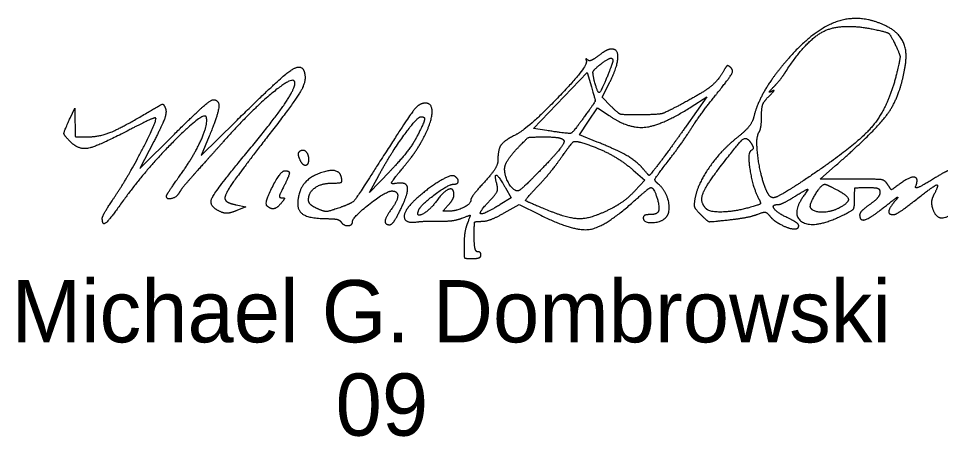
# Model space of a CAD drawing. Extents: x 0 to 40.2, y 0 to 22.
# Drawn here: x 37.037 to 39.11, y 9.704 to 10.644 of the extents above; entities that cross this region are included whole.
import ezdxf

# ---------------------------------------------------------------- set-up
doc = ezdxf.new("R2010")
doc.units = 0
doc.layers.add('SH_Text', color=7, linetype='Continuous')

msp = doc.modelspace()

# ---------------------------------------------------------------- linework, layer by layer
at = {"layer": 'SH_Text'}
for p, q in [((37.6689, 10.3288), (37.6689, 10.3288)), ((37.5957, 10.223), (37.5957, 10.223)), ((37.2255, 10.1947), (37.2255, 10.1947))]:
    msp.add_line(p, q, dxfattribs=at)
for points in [[(38.2249, 10.3922), (38.1945, 10.3971), (38.3154, 10.5228), (38.3249, 10.4906)], [(38.3688, 10.4472), (38.3489, 10.467), (38.3648, 10.4981)], [(38.5493, 10.4456), (38.5844, 10.4678), (38.5376, 10.4018)], [(37.153, 10.4197), (37.1634, 10.4425), (37.1641, 10.4102)], [(38.3382, 10.3664), (38.298, 10.3828), (38.3184, 10.4132), (38.3389, 10.4436), (38.3647, 10.4259)], [(37.4659, 10.3796), (37.4479, 10.3361), (37.5249, 10.4121)], [(37.3414, 10.3677), (37.3101, 10.307), (37.3876, 10.3842)], [(38.4187, 10.3034), (38.4453, 10.2805), (38.4225, 10.2563)], [(38.9111, 10.2829), (38.8389, 10.2829), (38.8737, 10.3133)], [(37.8715, 10.3001), (37.8261, 10.2525), (37.8469, 10.2911)], [(38.1316, 10.2636), (38.1447, 10.2406), (38.1202, 10.2257)], [(37.5263, 10.2252), (37.5485, 10.2207), (37.5276, 10.2121)], [(38.129, 10.2071), (38.1622, 10.2261), (38.2081, 10.2032)]]:
    msp.add_lwpolyline(points, dxfattribs=at)
for points in [[(38.9887, 10.6266), (38.9318, 10.655), (38.8265, 10.6208), (38.7688, 10.5553)], [(38.7607, 10.5229), (38.8078, 10.5965), (38.8883, 10.6353), (38.9617, 10.6196)], [(38.9617, 10.6196), (38.9893, 10.6138), (38.9972, 10.6079), (39.0077, 10.5859)], [(39.0304, 10.5375), (39.0358, 10.5703), (39.0158, 10.613), (38.9887, 10.6266)], [(38.3703, 10.5755), (38.3646, 10.5755), (38.3514, 10.5688), (38.3409, 10.5605)], [(38.3648, 10.4981), (38.3831, 10.534), (38.386, 10.5755), (38.3703, 10.5755)], [(39.0077, 10.5859), (39.0185, 10.5631), (39.019, 10.5536), (39.0113, 10.5217)], [(38.3165, 10.551), (38.3135, 10.554), (38.3122, 10.5528), (38.3135, 10.5483)], [(38.3409, 10.5605), (38.3305, 10.5523), (38.3195, 10.548), (38.3165, 10.551)], [(38.3429, 10.5392), (38.3589, 10.5521), (38.3731, 10.5568), (38.3731, 10.549)], [(38.7688, 10.5553), (38.7352, 10.5171), (38.6973, 10.4533), (38.6897, 10.4222)], [(37.5249, 10.4121), (37.6193, 10.5054), (37.6718, 10.5443), (37.6787, 10.5262)], [(38.3135, 10.5483), (38.3172, 10.5365), (38.1841, 10.3976), (38.1548, 10.3827)], [(38.3315, 10.505), (38.3275, 10.5211), (38.33, 10.5288), (38.3429, 10.5392)], [(38.3731, 10.549), (38.3731, 10.547), (38.3676, 10.5317), (38.3609, 10.5148)], [(38.6078, 10.4763), (38.6357, 10.5111), (38.6446, 10.5274), (38.6387, 10.5332)], [(38.6387, 10.5332), (38.6329, 10.5389), (38.6283, 10.5374), (38.623, 10.5279)], [(38.8737, 10.3133), (38.9659, 10.394), (39.0193, 10.4704), (39.0304, 10.5375)], [(37.6787, 10.5262), (37.6856, 10.5082), (37.6636, 10.4649), (37.6168, 10.4045)], [(38.3609, 10.5148), (38.3465, 10.479), (38.3387, 10.4764), (38.3315, 10.505)], [(38.623, 10.5279), (38.6099, 10.5047), (38.5766, 10.4779), (38.5292, 10.4525)], [(38.7341, 10.4898), (38.7424, 10.4982), (38.7544, 10.5131), (38.7607, 10.5229)], [(39.0113, 10.5217), (38.9925, 10.4431), (38.916, 10.3551), (38.7996, 10.2782)], [(37.6567, 10.504), (37.6489, 10.5118), (37.558, 10.4347), (37.5055, 10.376)], [(37.5636, 10.3589), (37.6178, 10.4243), (37.6641, 10.4966), (37.6567, 10.504)], [(38.3249, 10.4906), (38.334, 10.4597), (38.3335, 10.4573), (38.3096, 10.4239)], [(38.7303, 10.4805), (38.724, 10.4772), (38.7257, 10.4813), (38.7341, 10.4898)], [(38.5495, 10.397), (38.56, 10.4138), (38.5862, 10.4494), (38.6078, 10.4763)], [(38.7074, 10.4251), (38.7074, 10.4442), (38.713, 10.4586), (38.7246, 10.4699)], [(38.7246, 10.4699), (38.734, 10.4791), (38.7366, 10.4838), (38.7303, 10.4805)], [(37.3256, 10.4319), (37.3586, 10.4513), (37.3634, 10.4524), (37.3677, 10.4411)], [(37.3876, 10.3842), (37.4303, 10.4267), (37.4694, 10.4615), (37.4745, 10.4615)], [(37.4745, 10.4615), (37.4892, 10.4615), (37.4856, 10.4273), (37.4659, 10.3796)], [(37.9517, 10.4539), (37.9377, 10.4539), (37.9118, 10.4203), (37.8441, 10.3142)], [(37.9467, 10.374), (37.9655, 10.4096), (37.9682, 10.4539), (37.9517, 10.4539)], [(38.436, 10.4276), (38.3949, 10.4273), (38.386, 10.4299), (38.3688, 10.4472)], [(38.5292, 10.4525), (38.4918, 10.4324), (38.4745, 10.4278), (38.436, 10.4276)], [(37.1903, 10.3779), (37.2182, 10.3779), (37.2673, 10.3975), (37.3256, 10.4319)], [(37.3677, 10.4411), (37.3706, 10.4333), (37.3603, 10.4044), (37.3414, 10.3677)], [(38.3647, 10.4259), (38.4089, 10.3957), (38.4832, 10.4036), (38.5493, 10.4456)], [(37.1546, 10.3663), (37.1394, 10.3814), (37.1392, 10.3896), (37.153, 10.4197)], [(37.1641, 10.4102), (37.1647, 10.3787), (37.1653, 10.3779), (37.1903, 10.3779)], [(37.2529, 10.2422), (37.2827, 10.2864), (37.3498, 10.4157), (37.3452, 10.4203)], [(37.4597, 10.4215), (37.4564, 10.4382), (37.3228, 10.3048), (37.2733, 10.2354)], [(37.3452, 10.4203), (37.3437, 10.4218), (37.3168, 10.4096), (37.2855, 10.3932)], [(37.3964, 10.2856), (37.4293, 10.3313), (37.463, 10.4039), (37.4597, 10.4215)], [(37.8469, 10.2911), (37.8713, 10.3365), (37.9336, 10.4233), (37.9418, 10.4234)], [(37.9418, 10.4234), (37.9513, 10.4235), (37.9483, 10.4092), (37.9322, 10.3777)], [(38.3096, 10.4239), (38.2836, 10.3877), (38.2746, 10.3843), (38.2249, 10.3922)], [(38.6897, 10.4222), (38.6869, 10.4111), (38.6709, 10.391), (38.654, 10.3776)], [(38.701, 10.3871), (38.7045, 10.3925), (38.7073, 10.4096), (38.7074, 10.4251)], [(37.2855, 10.3932), (37.2162, 10.3569), (37.1729, 10.348), (37.1546, 10.3663)], [(37.6168, 10.4045), (37.5391, 10.3041), (37.4988, 10.2458), (37.5014, 10.2378)], [(38.5376, 10.4018), (38.5119, 10.3654), (38.4836, 10.3264), (38.4746, 10.315)], [(38.4975, 10.3236), (38.5156, 10.3472), (38.539, 10.3802), (38.5495, 10.397)], [(38.7164, 10.262), (38.7041, 10.2935), (38.694, 10.376), (38.701, 10.3871)], [(37.5055, 10.376), (37.4748, 10.3417), (37.4394, 10.3021), (37.4269, 10.2881)], [(37.9322, 10.3777), (37.9237, 10.3612), (37.8964, 10.3262), (37.8715, 10.3001)], [(37.9002, 10.307), (37.917, 10.3272), (37.9379, 10.3573), (37.9467, 10.374)], [(38.1548, 10.3827), (38.1281, 10.369), (38.1147, 10.3497), (38.1147, 10.325)], [(38.1561, 10.3494), (38.1797, 10.375), (38.1861, 10.3779), (38.2202, 10.3779)], [(38.263, 10.3701), (38.2656, 10.3659), (38.2447, 10.3385), (38.2166, 10.3093)], [(38.2202, 10.3779), (38.2411, 10.3779), (38.2603, 10.3744), (38.263, 10.3701)], [(38.2593, 10.3343), (38.2795, 10.3631), (38.2878, 10.3695), (38.3003, 10.3658)], [(38.3003, 10.3658), (38.3361, 10.3554), (38.3938, 10.3249), (38.4187, 10.3034)], [(38.4416, 10.3056), (38.4279, 10.3221), (38.3844, 10.3477), (38.3382, 10.3664)], [(38.654, 10.3776), (38.6178, 10.349), (38.5647, 10.2737), (38.5583, 10.2421)], [(38.6144, 10.3104), (38.6571, 10.3663), (38.6743, 10.3792), (38.6845, 10.3629)], [(37.4959, 10.2077), (37.4632, 10.2202), (37.4803, 10.2583), (37.5636, 10.3589)], [(37.6689, 10.3288), (37.6664, 10.3353), (37.6663, 10.3425), (37.6686, 10.3448)], [(37.6686, 10.3448), (37.6753, 10.3514), (37.6891, 10.3401), (37.6891, 10.328)], [(38.1299, 10.3055), (38.1299, 10.314), (38.1417, 10.3337), (38.1561, 10.3494)], [(38.6835, 10.3468), (38.6752, 10.3416), (38.6875, 10.2647), (38.7008, 10.2396)], [(38.6845, 10.3629), (38.6889, 10.3558), (38.6886, 10.3499), (38.6835, 10.3468)], [(37.6891, 10.328), (37.6891, 10.3135), (37.6746, 10.314), (37.6689, 10.3288)], [(38.1147, 10.325), (38.1147, 10.3163), (38.101, 10.2943), (38.0843, 10.2762)], [(38.207, 10.2696), (38.2218, 10.2853), (38.2453, 10.3144), (38.2593, 10.3343)], [(38.4757, 10.2715), (38.4662, 10.2793), (38.4694, 10.287), (38.4975, 10.3236)], [(37.5957, 10.223), (37.5894, 10.2293), (37.6265, 10.3019), (37.636, 10.3019)], [(37.636, 10.3019), (37.6466, 10.3019), (37.6453, 10.2894), (37.6319, 10.2635)], [(37.7632, 10.2861), (37.7581, 10.311), (37.679, 10.2845), (37.6696, 10.2546)], [(37.8441, 10.3142), (37.7965, 10.2396), (37.7865, 10.2284), (37.7592, 10.2187)], [(37.8829, 10.2728), (37.8737, 10.2712), (37.879, 10.2816), (37.9002, 10.307)], [(38.1595, 10.2563), (38.1496, 10.2563), (38.1299, 10.2891), (38.1299, 10.3055)], [(38.2166, 10.3093), (38.1884, 10.2802), (38.1627, 10.2563), (38.1595, 10.2563)], [(38.4746, 10.315), (38.4557, 10.291), (38.4541, 10.2905), (38.4416, 10.3056)], [(38.5833, 10.2158), (38.5689, 10.2302), (38.5807, 10.2662), (38.6144, 10.3104)], [(39.1282, 10.3019), (39.1256, 10.3019), (39.1069, 10.2918), (39.0868, 10.2794)], [(37.3699, 10.2449), (37.3699, 10.247), (37.3818, 10.2653), (37.3964, 10.2856)], [(37.4269, 10.2881), (37.4143, 10.274), (37.4013, 10.2577), (37.398, 10.2518)], [(37.7427, 10.274), (37.7597, 10.274), (37.7651, 10.2772), (37.7632, 10.2861)], [(38.017, 10.2898), (38.0096, 10.2944), (37.9525, 10.2591), (37.9261, 10.2338)], [(38.0147, 10.2715), (38.0249, 10.2715), (38.0265, 10.2839), (38.017, 10.2898)], [(38.1126, 10.2711), (38.1066, 10.2939), (38.1165, 10.2901), (38.1316, 10.2636)], [(38.9911, 10.2704), (38.9847, 10.2806), (38.9698, 10.2829), (38.9111, 10.2829)], [(39.0541, 10.2672), (39.0612, 10.2855), (39.0411, 10.289), (39.0197, 10.2732)], [(37.6319, 10.2635), (37.624, 10.2483), (37.6231, 10.2411), (37.629, 10.2411)], [(37.6891, 10.236), (37.6891, 10.2533), (37.7183, 10.274), (37.7427, 10.274)], [(37.896, 10.2148), (37.9143, 10.2524), (37.9086, 10.2776), (37.8829, 10.2728)], [(37.937, 10.2135), (37.9418, 10.2252), (38.0038, 10.2715), (38.0147, 10.2715)], [(38.0159, 10.2474), (38.0159, 10.264), (37.9936, 10.2564), (37.9772, 10.2341)], [(38.0843, 10.2762), (38.0676, 10.258), (38.0539, 10.2398), (38.0539, 10.2358)], [(38.0953, 10.2331), (38.1097, 10.2482), (38.1154, 10.2605), (38.1126, 10.2711)], [(38.2331, 10.2104), (38.1779, 10.2326), (38.176, 10.2369), (38.207, 10.2696)], [(38.4244, 10.2365), (38.4411, 10.2516), (38.4565, 10.2639), (38.4588, 10.2639)], [(38.4588, 10.2639), (38.4654, 10.2639), (38.4796, 10.2171), (38.4751, 10.2098)], [(38.4935, 10.1979), (38.5037, 10.2102), (38.4922, 10.2578), (38.4757, 10.2715)], [(38.734, 10.2411), (38.7288, 10.2411), (38.7209, 10.2505), (38.7164, 10.262)], [(38.7996, 10.2782), (38.7688, 10.2578), (38.7393, 10.2411), (38.734, 10.2411)], [(38.8178, 10.2181), (38.8138, 10.2245), (38.8421, 10.2715), (38.8499, 10.2715)], [(38.8499, 10.2715), (38.8514, 10.2715), (38.8627, 10.2663), (38.8751, 10.2599)], [(38.9165, 10.2374), (38.9165, 10.2626), (38.9182, 10.2639), (38.9507, 10.2639)], [(38.9507, 10.2639), (38.9654, 10.2639), (38.9735, 10.26), (38.9735, 10.253)], [(39.0197, 10.2732), (39.0008, 10.2592), (38.9983, 10.2589), (38.9911, 10.2704)], [(39.0504, 10.2335), (39.093, 10.2672), (39.1076, 10.2721), (39.0949, 10.2484)], [(39.0868, 10.2794), (39.0666, 10.267), (39.052, 10.2615), (39.0541, 10.2672)], [(37.2255, 10.1947), (37.2255, 10.1985), (37.2378, 10.2199), (37.2529, 10.2422)], [(37.398, 10.2518), (37.3924, 10.2419), (37.3699, 10.2363), (37.3699, 10.2449)], [(37.629, 10.2411), (37.6353, 10.2411), (37.635, 10.2378), (37.6283, 10.2297)], [(37.6696, 10.2546), (37.6587, 10.2205), (37.6859, 10.194), (37.7318, 10.194)], [(37.7879, 10.1872), (37.7879, 10.1971), (37.8637, 10.2563), (37.8763, 10.2563)], [(37.8763, 10.2563), (37.8899, 10.2563), (37.8892, 10.2336), (37.875, 10.2149)], [(38.0033, 10.2246), (38.0102, 10.2322), (38.0159, 10.2425), (38.0159, 10.2474)], [(38.4225, 10.2563), (38.4099, 10.243), (38.3866, 10.2254), (38.3707, 10.2172)], [(38.5583, 10.2421), (38.555, 10.2254), (38.5581, 10.2157), (38.5708, 10.203)], [(38.7008, 10.2396), (38.7064, 10.2289), (38.7026, 10.2252), (38.679, 10.2187)], [(38.745, 10.2259), (38.7496, 10.2259), (38.7679, 10.235), (38.7855, 10.2461)], [(38.7855, 10.2461), (38.8032, 10.2573), (38.8139, 10.2616), (38.8094, 10.2556)], [(38.8094, 10.2556), (38.7706, 10.2055), (38.8244, 10.1695), (38.8899, 10.2017)], [(38.8751, 10.2599), (38.9009, 10.2465), (38.904, 10.2299), (38.8828, 10.2186)], [(38.9735, 10.253), (38.9735, 10.247), (38.9632, 10.2348), (38.9507, 10.2259)], [(38.9879, 10.2236), (39.0071, 10.2391), (39.0169, 10.2448), (39.0096, 10.2363)], [(39.0949, 10.2484), (39.0904, 10.2399), (39.0888, 10.2262), (39.0914, 10.218)], [(37.2733, 10.2354), (37.242, 10.1917), (37.2255, 10.1776), (37.2255, 10.1947)], [(37.5014, 10.2378), (37.5029, 10.2333), (37.5141, 10.2277), (37.5263, 10.2252)], [(37.6283, 10.2297), (37.6185, 10.2178), (37.6039, 10.2149), (37.5957, 10.223)], [(37.7086, 10.2167), (37.6979, 10.2216), (37.6891, 10.2302), (37.6891, 10.236)], [(37.7592, 10.2187), (37.7347, 10.21), (37.7241, 10.2096), (37.7086, 10.2167)], [(37.9261, 10.2338), (37.9025, 10.211), (37.9061, 10.1831), (37.9323, 10.1866)], [(37.9772, 10.2341), (37.961, 10.2122), (37.9299, 10.1963), (37.937, 10.2135)], [(38.0029, 10.2107), (37.9919, 10.2107), (37.9919, 10.212), (38.0033, 10.2246)], [(38.0539, 10.2358), (38.0539, 10.2271), (38.0206, 10.2107), (38.0029, 10.2107)], [(38.1202, 10.2257), (38.083, 10.203), (38.0701, 10.2068), (38.0953, 10.2331)], [(38.2081, 10.2032), (38.2856, 10.1644), (38.3568, 10.1754), (38.4244, 10.2365)], [(38.679, 10.2187), (38.6469, 10.2098), (38.591, 10.2081), (38.5833, 10.2158)], [(38.7666, 10.1955), (38.7426, 10.2068), (38.729, 10.2259), (38.745, 10.2259)], [(38.8899, 10.2017), (38.9114, 10.2123), (38.9165, 10.2191), (38.9165, 10.2374)], [(38.9507, 10.2259), (38.9381, 10.217), (38.9279, 10.2065), (38.9279, 10.2026)], [(38.9279, 10.2026), (38.9279, 10.1874), (38.9545, 10.1967), (38.9879, 10.2236)], [(39.0096, 10.2363), (38.9948, 10.2192), (38.9921, 10.2031), (39.0041, 10.2031)], [(39.0041, 10.2031), (39.0084, 10.2031), (39.0292, 10.2168), (39.0504, 10.2335)], [(39.0914, 10.218), (39.0994, 10.1926), (39.1346, 10.1996), (39.19, 10.2375)], [(37.5276, 10.2121), (37.5162, 10.2074), (37.5019, 10.2054), (37.4959, 10.2077)], [(37.875, 10.2149), (37.8622, 10.1979), (37.8604, 10.1803), (37.8716, 10.1803)], [(37.8716, 10.1803), (37.8758, 10.1803), (37.8868, 10.1958), (37.896, 10.2148)], [(38.034, 10.1952), (38.0523, 10.2021), (38.0529, 10.2016), (38.046, 10.1833)], [(38.0786, 10.188), (38.088, 10.188), (38.1107, 10.1966), (38.129, 10.2071)], [(38.3707, 10.2172), (38.3274, 10.1949), (38.2776, 10.1925), (38.2331, 10.2104)], [(38.4562, 10.2031), (38.4481, 10.2031), (38.4415, 10.1997), (38.4415, 10.1955)], [(38.4751, 10.2098), (38.4729, 10.2061), (38.4643, 10.2031), (38.4562, 10.2031)], [(38.5708, 10.203), (38.5859, 10.1879), (38.5925, 10.1867), (38.6331, 10.1913)], [(38.6331, 10.1913), (38.6581, 10.1941), (38.6872, 10.1997), (38.6977, 10.2037)], [(38.6977, 10.2037), (38.712, 10.2091), (38.7192, 10.2083), (38.7255, 10.2004)], [(38.7255, 10.2004), (38.7302, 10.1946), (38.7409, 10.186), (38.7493, 10.1815)], [(38.8828, 10.2186), (38.8642, 10.2086), (38.8238, 10.2083), (38.8178, 10.2181)], [(37.7318, 10.194), (37.746, 10.194), (37.7594, 10.1909), (37.7618, 10.1871)], [(37.7618, 10.1871), (37.7673, 10.1782), (37.7879, 10.1783), (37.7879, 10.1872)], [(37.9323, 10.1866), (37.9427, 10.188), (37.9656, 10.1888), (37.983, 10.1885)], [(37.983, 10.1885), (38.0005, 10.1881), (38.0234, 10.1911), (38.034, 10.1952)], [(38.046, 10.1833), (38.042, 10.1727), (38.0387, 10.1506), (38.0387, 10.1342)], [(38.0615, 10.1537), (38.0615, 10.1841), (38.0634, 10.1879), (38.0786, 10.188)], [(38.4415, 10.1955), (38.4415, 10.1843), (38.4839, 10.1862), (38.4935, 10.1979)], [(38.7493, 10.1815), (38.7669, 10.1719), (38.7912, 10.1701), (38.7909, 10.1784)], [(38.7909, 10.1784), (38.7908, 10.1815), (38.7799, 10.1892), (38.7666, 10.1955)], [(38.0691, 10.1195), (38.0649, 10.1195), (38.0615, 10.1349), (38.0615, 10.1537)], [(38.0387, 10.1342), (38.0387, 10.1074), (38.0406, 10.1043), (38.0577, 10.1043)], [(38.0767, 10.1119), (38.0767, 10.1161), (38.0733, 10.1195), (38.0691, 10.1195)], [(38.0577, 10.1043), (38.0681, 10.1043), (38.0767, 10.1077), (38.0767, 10.1119)]]:
    msp.add_open_spline(points, degree=2, dxfattribs=at)

# ---------------------------------------------------------------- texts
for s, p in [('Michael G. Dombrowski', (37.0217, 9.9158)), ('              09', (37.0217, 9.7058))]:
    msp.add_text(s, height=0.14, dxfattribs=at).set_placement(p)

doc.saveas('drawing.dxf')
